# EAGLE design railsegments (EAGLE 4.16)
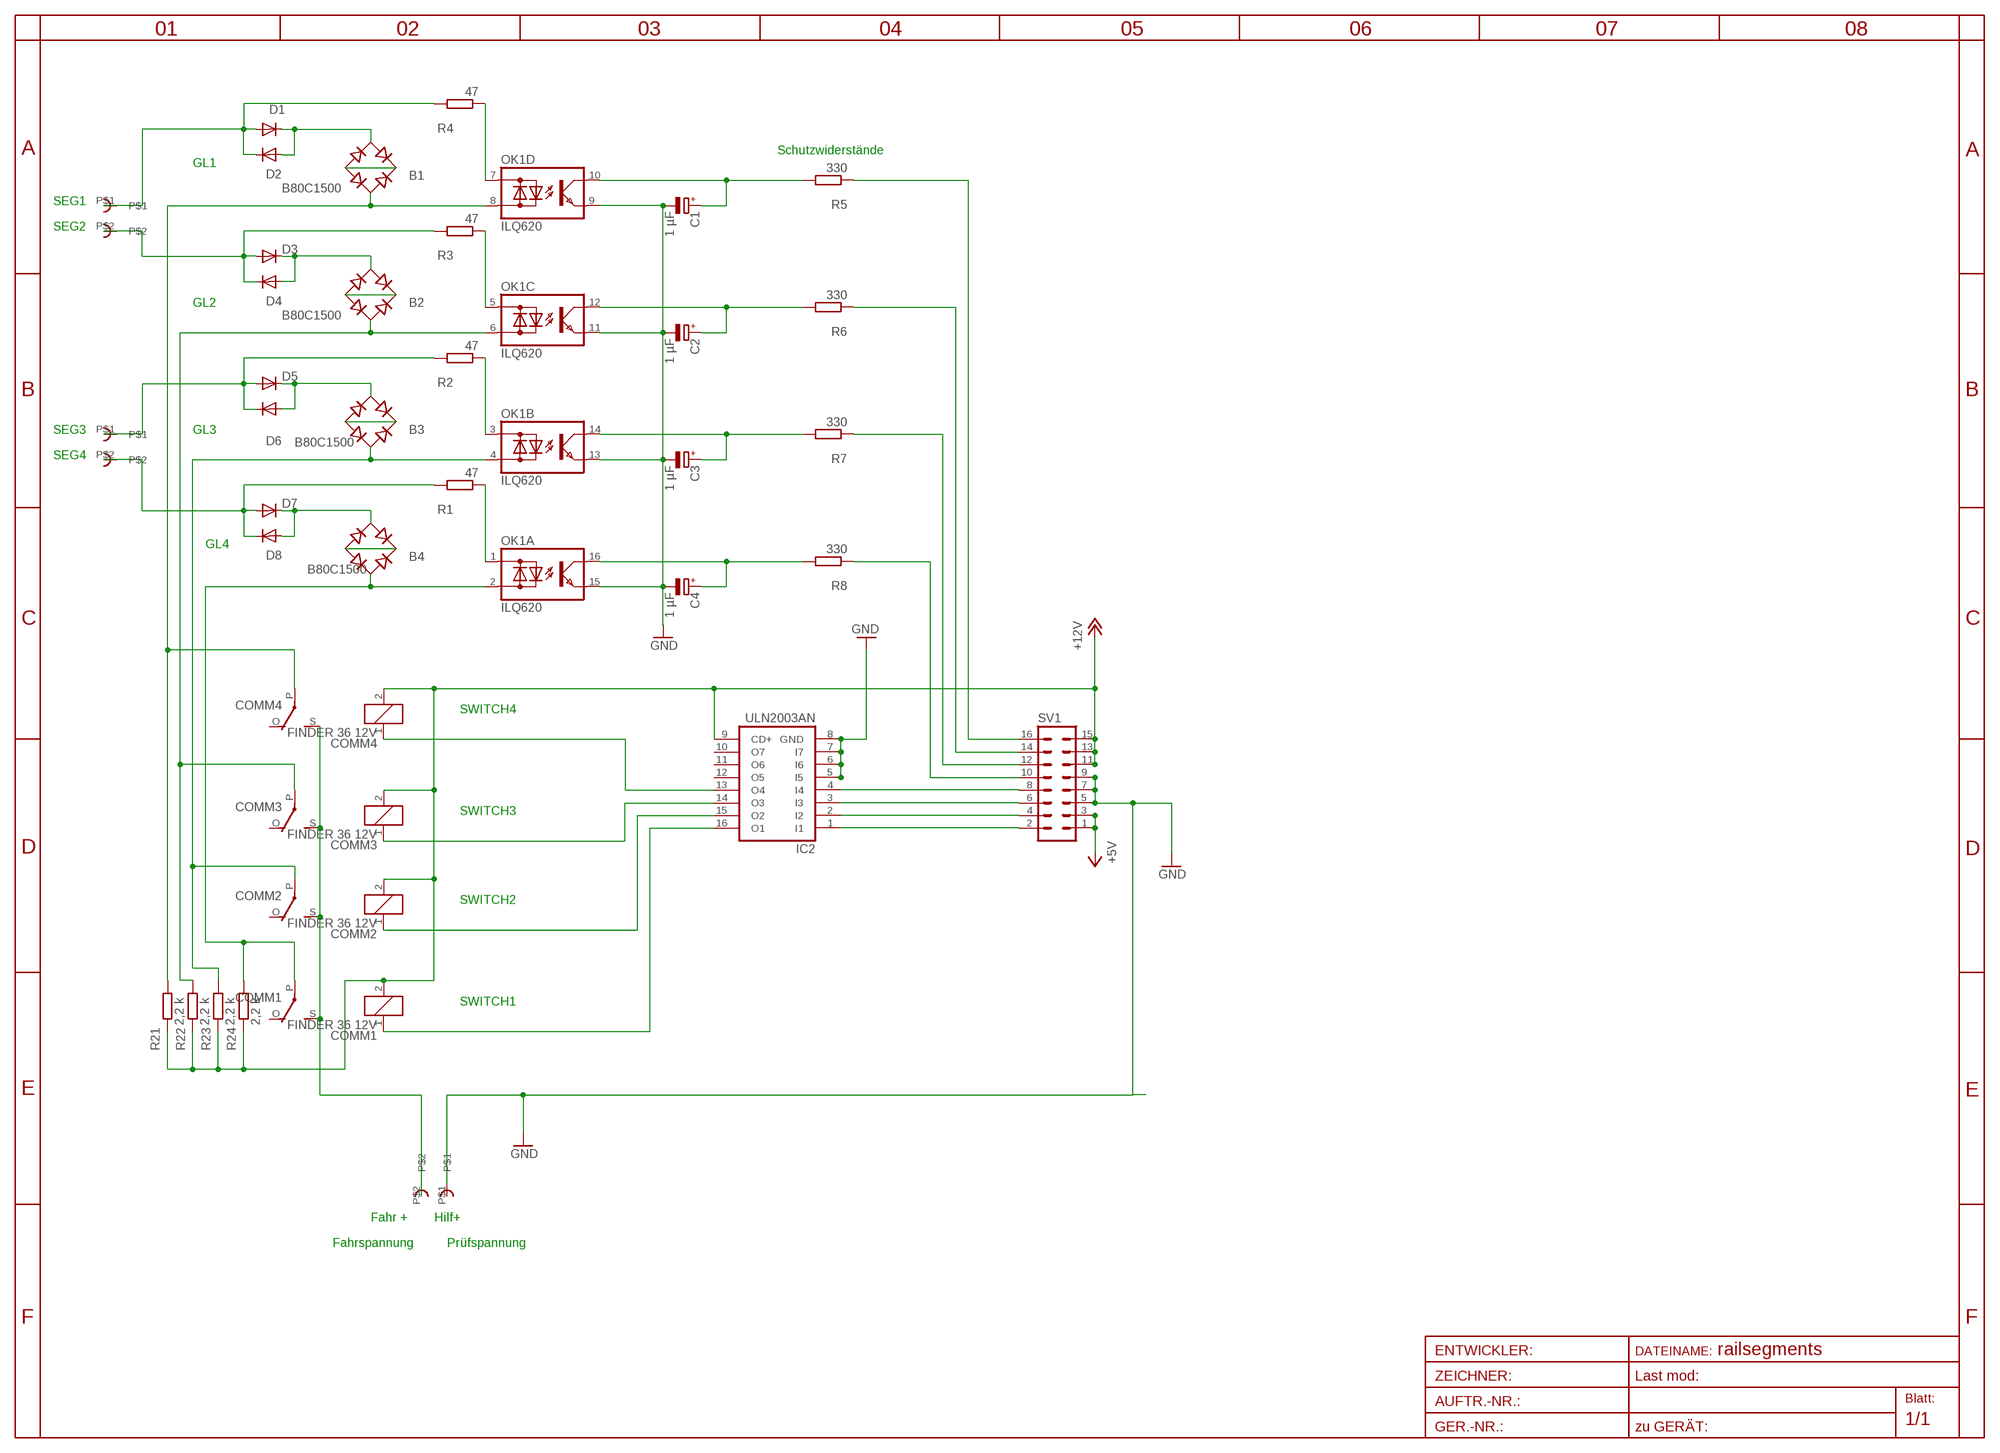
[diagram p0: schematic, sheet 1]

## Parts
B1  B80C1500  RECTIFIER-RB1A  [RB1A]
B2  B80C1500  RECTIFIER-RB1A  [RB1A]
B3  B80C1500  RECTIFIER-RB1A  [RB1A]
B4  B80C1500  RECTIFIER-RB1A  [RB1A]
C1  1 µF  CPOL-EUE2-4  [E2-4]
C2  1 µF  CPOL-EUE2-4  [E2-4]
C3  1 µF  CPOL-EUE2-4  [E2-4]
C4  1 µF  CPOL-EUE2-4  [E2-4]
COMM1  FINDER 36 12V  G5L  [G5LE]
COMM2  FINDER 36 12V  G5L  [G5LE]
COMM3  FINDER 36 12V  G5L  [G5LE]
COMM4  FINDER 36 12V  G5L  [G5LE]
D1  DIODE-D-2.5  [D-2.5]
D2  DIODE-D-2.5  [D-2.5]
D3  DIODE-D-2.5  [D-2.5]
D4  DIODE-D-2.5  [D-2.5]
D5  DIODE-D-2.5  [D-2.5]
D6  DIODE-D-2.5  [D-2.5]
D7  DIODE-D-2.5  [D-2.5]
D8  DIODE-D-2.5  [D-2.5]
IC2  ULN2003AN  [DIL16]
OK1  ILQ620  [DIL16]
PRUEFSPANNUNG  RIACON101-2  [RIACON101-2]
PRUEFSPANNUNG3  RIACON101-2  [RIACON101-2]
PRUEFSPANNUNG4  RIACON101-2  [RIACON101-2]
R1  47  R-EU_0204/5  [0204/5]
R2  47  R-EU_0204/5  [0204/5]
R3  47  R-EU_0204/5  [0204/5]
R4  47  R-EU_0204/5  [0204/5]
R5  330  R-EU_0204/2V  [0204V]
R6  330  R-EU_0204/2V  [0204V]
R7  330  R-EU_0204/2V  [0204V]
R8  330  R-EU_0204/2V  [0204V]
R21  2,2 k  R-EU_0204/2V  [0204V]
R22  2,2 k  R-EU_0204/2V  [0204V]
R23  2,2 k  R-EU_0204/2V  [0204V]
R24  2,2 k  R-EU_0204/2V  [0204V]
SV1  ML16  [ML16]

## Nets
+5V: SV1.1 SV1.3
+12V: COMM1.2 COMM2.2 COMM3.2 COMM4.2 IC2.9(CD+) R21.1 R22.1 R23.1 R24.1 SV1.11 SV1.13 SV1.15
GND: C1.- C2.- C3.- C4.- IC2.5(I5) IC2.6(I6) IC2.7(I7) IC2.8(GND) OK1.9(D:E) OK1.11(C:E) OK1.13(B:E) OK1.15(A:E) SV1.5 SV1.7 SV1.9
IN_1: IC2.1(I1) SV1.2
IN_2: IC2.2(I2) SV1.4
IN_3: IC2.3(I3) SV1.6
IN_4: IC2.4(I4) SV1.8
N$2: OK1.7(D:AC1) R4.1
N$3: OK1.1(A:AC1) R1.1
N$10: B1.+ B1.-
N$11: B2.+ B2.-
N$12: B3.+ B3.-
N$13: B4.+ B4.-
N$17: B1.AC1 D1.C D2.A
N$18: B4.AC1 D7.C D8.A
OPTO_OUT_1: C1.+ OK1.10(D:C) R5.2
OPTO_OUT_2: C2.+ OK1.12(C:C) R6.2
OPTO_OUT_3: C3.+ OK1.14(B:C) R7.2
OPTO_OUT_4: C4.+ OK1.16(A:C) R8.2
OUT_1: R5.1 SV1.16
OUT_2: R6.1 SV1.14
OUT_3: R7.1 SV1.12
OUT_4: R8.1 SV1.10
RAILPOWER_PLUS: COMM1.S(2:S) COMM2.S(2:S) COMM3.S(2:S) COMM4.S(2:S) PRUEFSPANNUNG.P$2
RELAY_DRIVE_1: COMM1.1 IC2.16(O1)
RELAY_DRIVE_2: COMM2.1 IC2.15(O2)
RELAY_DRIVE_3: COMM3.1 IC2.14(O3)
RELAY_DRIVE_4: COMM4.1 IC2.13(O4)
SEG1: D1.A D2.C PRUEFSPANNUNG4.P$1 R4.2
SEG2: B2.AC1 D3.C D4.A
SEG3: B3.AC1 D5.C D6.A
SEG5: D3.A D4.C PRUEFSPANNUNG4.P$2 R3.2
SEG6: D5.A D6.C PRUEFSPANNUNG3.P$1 R2.2
SEG7: D7.A D8.C PRUEFSPANNUNG3.P$2 R1.2
SEG_SW1: B1.AC2 COMM4.P(2:P) OK1.8(D:AC2) R21.2
SEG_SW2: B2.AC2 COMM3.P(2:P) OK1.6(C:AC2) R22.2
SEG_SW2A: OK1.5(C:AC1) R3.1
SEG_SW3: B3.AC2 COMM2.P(2:P) OK1.4(B:AC2) R23.2
SEG_SW3A: OK1.3(B:AC1) R2.1
SEG_SW4: B4.AC2 COMM1.P(2:P) OK1.2(A:AC2) R24.2
Unconnected: COMM1.O(2:O) COMM2.O(2:O) COMM3.O(2:O) COMM4.O(2:O) IC2.10(O7) IC2.11(O6) IC2.12(O5) PRUEFSPANNUNG.P$1

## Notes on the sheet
- Schutzwiderstände
- GL1
- SEG1
- SEG2
- GL2
- SEG3 | GL3
- SEG4
- GL4
- SWITCH4
- SWITCH3
- SWITCH2
- SWITCH1
- Fahr + | Hilf+
- Fahrspannung | Prüfspannung

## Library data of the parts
B1-B4 = rectifier:RECTIFIER-: Rectifier
C1-C4 = rcl:CPOL-EU: POLARIZED CAPACITOR, European symbol
COMM1-COMM4 = relay:G5L: RELAY 1 x switch, 10 A/120 V AC, 8 A/30 V ADC, Omron
D1-D8 = diode:DIODE-: DIODE
IC2 = uln-udn:ULN2003A: DRIVER ARRAY
OK1 = optocoupler:ILQ620: SIEMENS OPTO COUPLER
PRUEFSPANNUNG PRUEFSPANNUNG3 PRUEFSPANNUNG4 = con-riacon101:RIACON101-2: Riaconn Schreaubklemme 101
R1-R8 R21-R24 = rcl:R-EU_: RESISTOR, European symbol
SV1 = con-harting-ml:ML16: HARTING

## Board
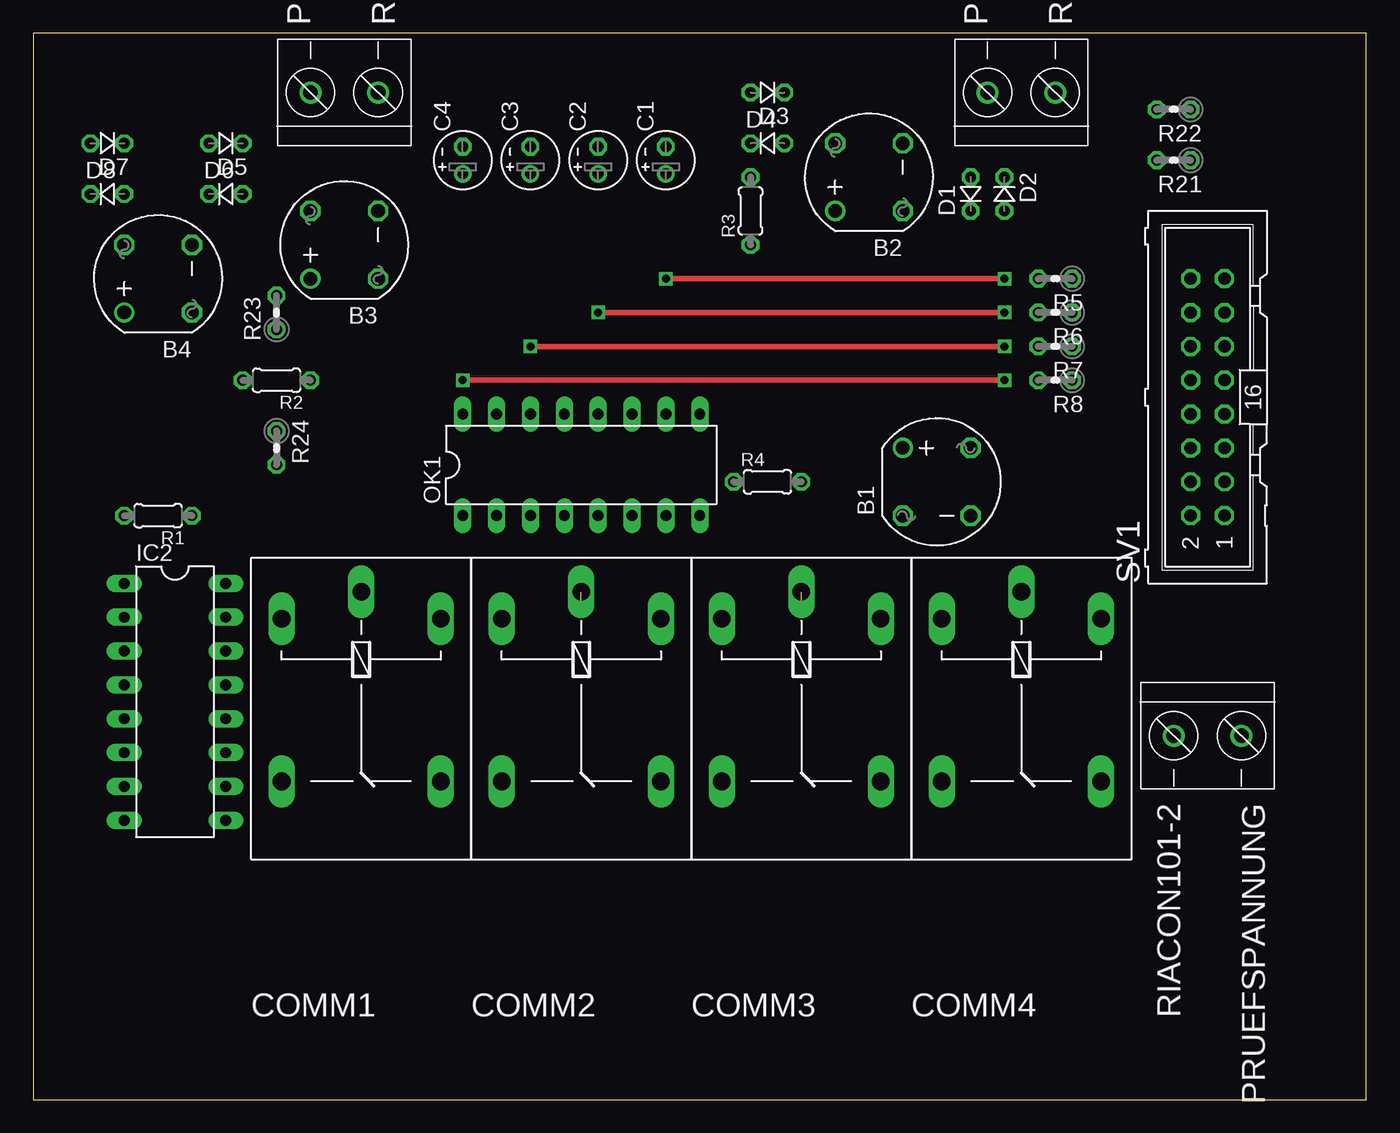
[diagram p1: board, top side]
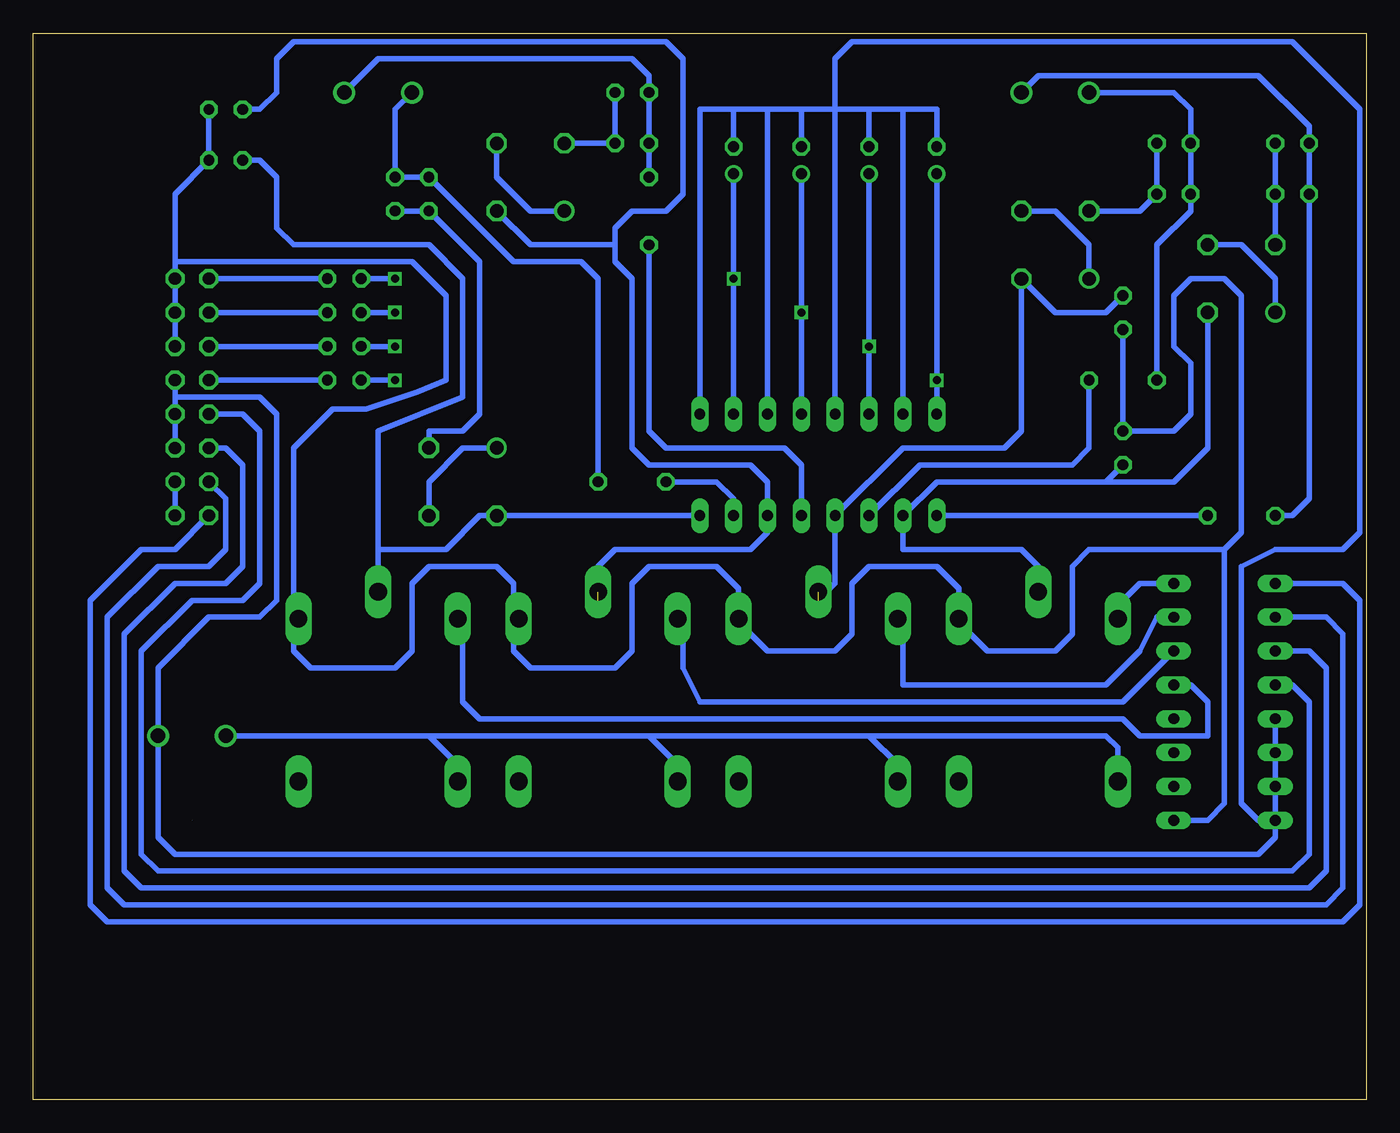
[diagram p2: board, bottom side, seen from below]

Size 100 x 80 mm. Coordinates in mm from the lower left corner, seen from the top.
Outline: 0,0 100,0 100,80 0,80 0,0
Copper layers (1*16): Top 0.035mm / dielectric 1.5mm / Bottom 0.035mm
Design rules "default": minimum track width 10mil, minimum drill 24mil, track to track 8mil, track to pad 8mil, pad to pad 8mil, via to via 8mil, smd to smd 8mil, copper to edge 40mil, drill to drill 8mil, minimum pad ring 10mil, minimum via ring 8mil, stop-mask expansion 4mil, vias tented up to drill 0mil, thermal gap 10mil

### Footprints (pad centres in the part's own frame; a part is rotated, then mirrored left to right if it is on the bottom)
RB1A = drill 1.016 round: + -2.54,2.54 | drill 1.016 octagon: - 2.54,-2.54; AC1 2.54,2.54; AC2 -2.54,-2.54
E2-4 = drill 0.813 pad 1.27 round: + -1.016,0 | drill 0.813 pad 1.27 octagon: - 1.016,0
G5LE = drill 1.321 long: 1 -7.493,-5.969; 2 -7.493,5.969; O 4.699,5.969; P -9.525,0; S 4.699,-5.969
D-2.5 = drill 0.813 octagon: A 1.27,0; C -1.27,0
DIL16 = drill 0.813 long: 1 -8.89,-3.81; 2 -6.35,-3.81; 3 -3.81,-3.81; 4 -1.27,-3.81; 5 1.27,-3.81; 6 3.81,-3.81; 7 6.35,-3.81; 8 8.89,-3.81; 9 8.89,3.81; 10 6.35,3.81; 11 3.81,3.81; 12 1.27,3.81; 13 -1.27,3.81; 14 -3.81,3.81; 15 -6.35,3.81; 16 -8.89,3.81
RIACON101-2 = drill 1.1 round: P$1 0,2.54; P$2 0,-2.54
0204/5 = drill 0.813 octagon: 1 -2.54,0; 2 2.54,0
0204V = drill 0.813 octagon: 1 -1.27,0; 2 1.27,0
ML16 = drill 0.914 octagon: 1 -8.89,-1.27; 2 -8.89,1.27; 3 -6.35,-1.27; 4 -6.35,1.27; 5 -3.81,-1.27; 6 -3.81,1.27; 7 -1.27,-1.27; 8 -1.27,1.27; 9 1.27,-1.27; 10 1.27,1.27; 11 3.81,-1.27; 12 3.81,1.27; 13 6.35,-1.27; 14 6.35,1.27; 15 8.89,-1.27; 16 8.89,1.27

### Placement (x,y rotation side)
B1  67.78,46.35 0 top
B2  62.7,69.21 90 top
B3  23.33,64.13 90 top
B4  9.36,61.59 90 top
C1  47.46,70.48 90 top
C2  42.38,70.48 90 top
C3  37.3,70.48 90 top
C4  32.22,70.48 90 top
COMM1  24.6,28.57 270 top
COMM2  41.11,28.57 270 top
COMM3  57.62,28.57 270 top
COMM4  74.13,28.57 270 top
D1  70.32,67.94 90 top
D2  72.86,67.94 270 top
D3  55.08,75.56 180 top
D4  55.08,71.75 0 top
D5  14.44,71.75 180 top
D6  14.44,67.94 0 top
D7  5.55,71.75 180 top
D8  5.55,67.94 0 top
IC2  10.63,29.84 270 top
OK1  41.11,47.62 0 top
PRUEFSPANNUNG  88.1,27.3 270 top
PRUEFSPANNUNG3  23.33,75.56 90 top
PRUEFSPANNUNG4  74.13,75.56 90 top
R1  9.36,43.81 180 top
R2  18.25,53.97 180 top
R3  53.81,66.67 90 top
R4  55.08,46.35 0 top
R5  76.67,61.59 180 top
R6  76.67,59.05 180 top
R7  76.67,56.51 180 top
R8  76.67,53.97 180 top
R21  85.56,70.48 180 top
R22  85.56,74.29 180 top
R23  18.25,59.05 90 top
R24  18.25,48.89 270 top
SV1  88.1,52.7 90 top

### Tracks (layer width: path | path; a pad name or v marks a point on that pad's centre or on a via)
+5V
  Bottom 0.406: SV1.3 SV1.1
+12V
  Bottom 0.406: SV1.15 SV1.13 | SV1.13 SV1.11 | SV1.15 SV1.13 | R22.1 R21.1 89.37,67.94 89.37,62.86 | R23.1 R24.1 14.44,50.16 13.17,51.43 13.17,55.24 14.44,56.51 14.44,60.32 13.17,61.59 10.63,61.59 9.36,60.32 9.36,42.54 10.63,41.27 | 89.37,62.86 SV1.15 | 80.48,36.19 COMM4.2 80.35,36.06 80.48,36.19 | 80.48,36.19 80.48,48.89 77.56,51.81 75.02,51.81 71.21,53.08 69.05,53.97 69.05,60.32 71.59,62.86 89.37,62.86 | 10.63,41.27 20.79,41.27 22.06,40 22.06,34.92 23.33,33.65 28.41,33.65 30.82,36.06 | 30.82,36.06 30.95,36.19 | 30.82,36.06 COMM1.2 30.57,38.35 32.22,40 37.3,40 38.57,38.73 38.57,34.92 39.84,33.65 44.92,33.65 47.33,36.06 | 47.46,36.19 47.33,36.06 | 47.33,36.06 COMM2.2 47.08,38.35 48.73,40 53.81,40 55.08,38.73 55.08,33.65 56.35,32.38 62.7,32.38 63.97,33.65 63.97,36.19 | COMM3.2 63.84,36.06 63.97,36.19 | IC2.9 11.9,20.95 10.63,22.22 10.63,41.27 | 63.97,36.19 63.97,38.73 65.24,40 70.32,40 71.59,38.73 71.59,33.65 72.86,32.38 79.21,32.38 80.48,33.65 80.48,36.19
GND
  Bottom 0.406: IC2.6 IC2.5 | IC2.7 IC2.6 | 89.37,52.7 SV1.7 SV1.5 89.37,52.7 | 89.37,52.7 83.02,52.7 81.75,51.43 81.75,37.46 83.02,36.19 86.83,36.19 90.64,32.38 90.64,19.68 89.37,18.41 8.09,18.41 6.82,19.68 IC2.8 | 89.37,52.7 SV1.9 | IC2.7 IC2.6 | IC2.8 IC2.7 | IC2.8 8.09,20.95 9.36,22.22 9.36,40 6.82,41.27 1.74,41.27 0.47,42.54 0.47,74.29 5.55,79.37 38.57,79.37 39.84,78.1 39.84,74.29 | C4.- 32.22,74.29 34.76,74.29 | 34.76,74.29 37.3,74.29 | 37.3,74.29 39.84,74.29 | 39.84,74.29 42.38,74.29 | 42.38,74.29 44.92,74.29 | 44.92,74.29 47.46,74.29 | 47.46,74.29 C1.- | 42.38,74.29 C2.- | 37.3,74.29 C3.- | OK1.15 34.76,74.29 | 39.84,74.29 OK1.13 | 44.92,74.29 OK1.11 | OK1.9 50,74.29 47.46,74.29
IN_1
  Bottom 0.406: IC2.1 1.74,38.73 0.47,37.46 0.47,14.6 1.74,13.33 94.45,13.33 95.72,14.6 95.72,37.46 91.91,41.27 89.37,41.27 SV1.2
IN_2
  Bottom 0.406: IC2.2 3.01,36.19 1.74,34.92 1.74,15.87 3.01,14.6 93.18,14.6 94.45,15.87 94.45,36.19 90.64,40 86.83,40 85.56,41.27 85.56,45.08 SV1.4
IN_3
  Bottom 0.406: IC2.3 4.28,33.65 3.01,32.38 3.01,17.14 4.28,15.87 91.91,15.87 93.18,17.14 93.18,34.92 89.37,38.73 85.56,38.73 84.29,40 84.29,47.62 85.56,48.89 SV1.6
IN_4
  Bottom 0.406: IC2.4 5.55,31.11 4.28,29.84 4.28,18.41 5.55,17.14 90.64,17.14 91.91,18.41 91.91,33.65 88.1,37.46 84.29,37.46 83.02,38.73 83.02,50.16 84.29,51.43 SV1.8
N$2
  Bottom 0.406: R4.1 48.73,46.35 47.46,45.08 OK1.7
N$3
  Bottom 0.406: OK1.1 R1.1
N$5  (1 unrouted)
N$10
  Bottom 0.406: B1.+ 67.78,48.89 70.32,46.35 B1.-
N$11
  Bottom 0.406: B2.- 65.24,69.21 62.7,66.67 B2.+
N$12
  Bottom 0.406: B3.+ 20.79,64.13 23.33,66.67 B3.-
N$13
  Bottom 0.406: B4.+ 6.82,61.59 9.36,64.13 B4.-
N$17
  Bottom 0.406: B1.AC1 70.32,50.16 67.78,50.16 66.51,51.43 66.51,62.86 D1.C D2.A
N$18
  Bottom 0.406: D7.C D8.A B4.AC1
OPTO_OUT_1  (via drill 0.6)
  Top 0.406: v47.46,61.59 v72.86,61.59
  Bottom 0.406: OK1.10 v47.46,61.59 C1.+ | v72.86,61.59 R5.2
OPTO_OUT_2  (via drill 0.6)
  Top 0.406: v42.38,59.05 v72.86,59.05
  Bottom 0.406: C2.+ v42.38,59.05 OK1.12 | v72.86,59.05 R6.2
OPTO_OUT_3  (via drill 0.6)
  Top 0.406: v37.3,56.51 v72.86,56.51
  Bottom 0.406: OK1.14 v37.3,56.51 C3.+ | v72.86,56.51 R7.2
OPTO_OUT_4  (via drill 0.6)
  Top 0.406: v32.22,53.97 v72.86,53.97
  Bottom 0.406: OK1.16 v32.22,53.97 C4.+ | v72.86,53.97 R8.2
OUT_1
  Bottom 0.406: R5.1 SV1.16
OUT_2
  Bottom 0.406: R6.1 SV1.14
OUT_3
  Bottom 0.406: R7.1 SV1.12
OUT_4
  Bottom 0.406: R8.1 SV1.10
RAILPOWER_PLUS
  Bottom 0.406: COMM1.S 18.63,26.41 19.52,27.3 37.3,27.3 | 37.3,27.3 53.81,27.3 | 53.81,27.3 70.32,27.3 | 70.32,27.3 PRUEFSPANNUNG.P$2 | COMM2.S 35.14,25.14 37.3,27.3 | COMM3.S 51.65,25.14 53.81,27.3 | COMM4.S 68.16,25.14 70.32,27.3
RELAY_DRIVE_1
  Bottom 0.406: IC2.16 16.98,38.73 18.25,37.46 18.25,36.19 18.38,36.06 COMM1.1
RELAY_DRIVE_2
  Bottom 0.406: IC2.15 15.71,36.19 16.98,33.65 19.52,31.11 34.76,31.11 34.76,36.19 34.89,36.06 COMM2.1
RELAY_DRIVE_3
  Bottom 0.406: IC2.14 18.25,29.84 50,29.84 51.27,32.38 51.27,36.19 51.4,36.06 COMM3.1
RELAY_DRIVE_4
  Bottom 0.406: IC2.13 13.17,31.11 11.9,29.84 11.9,27.3 16.98,27.3 18.25,28.57 66.51,28.57 67.78,29.84 67.78,36.19 67.91,36.06 COMM4.1
SEG1
  Bottom 0.406: PRUEFSPANNUNG4.P$1 72.86,74.29 D2.C D1.A 63.97,62.86 58.89,62.86 57.62,61.59 R4.2
SEG2
  Bottom 0.406: D3.C D4.A B2.AC1
SEG3
  Bottom 0.406: D5.C D6.A 16.98,66.67 B3.AC1
SEG5
  Bottom 0.406: R3.2 D4.C D3.A 53.81,76.83 55.08,78.1 74.13,78.1 PRUEFSPANNUNG4.P$2
SEG6
  Bottom 0.406: PRUEFSPANNUNG3.P$1 14.44,75.56 13.17,74.29 D5.A D6.C 13.17,66.67 15.71,64.13 R2.2
SEG7
  Bottom 0.406: R1.2 5.55,43.81 4.28,45.08 D8.C D7.A 4.28,73.02 8.09,76.83 24.6,76.83 PRUEFSPANNUNG3.P$2
SEG_SW1
  Bottom 0.406: OK1.8 B1.AC2 66.51,43.81 69.05,41.27 74.13,41.27 | R21.2 83.02,70.48 81.75,69.21 81.75,65.4 80.48,64.13 70.32,64.13 67.78,61.59 67.78,52.7 74.13,50.16 74.13,41.27 | 74.13,37.46 COMM4.P 74.13,41.27
SEG_SW2  (1 unrouted)
  Bottom 0.406: B2.AC2 62.7,64.13 56.35,64.13 | 56.35,64.13 56.35,62.86 55.08,61.59 55.08,48.89 53.81,47.62 46.19,47.62 44.92,46.35 OK1.6 44.92,42.54 46.19,41.27 56.35,41.27 57.62,40 57.62,37.46 | R22.2 83.02,74.29 81.75,75.56 81.75,78.1 80.48,79.37 52.54,79.37 51.27,78.1 51.27,67.94 52.54,66.67 55.08,66.67 56.35,65.4 56.35,64.13
SEG_SW2A
  Bottom 0.406: OK1.5 42.38,47.62 43.65,48.89 52.54,48.89 53.81,50.16 R3.1
SEG_SW3  (1 unrouted)
  Bottom 0.406: R23.2 19.52,59.05 23.33,59.05 B3.AC2 25.87,50.16 27.14,48.89 34.76,48.89 OK1.4 39.84,38.73 41.11,37.46
SEG_SW3A
  Bottom 0.406: OK1.3 33.49,47.62 22.06,47.62 20.79,48.89 R2.1
SEG_SW4
  Bottom 0.406: COMM1.P 24.6,40 25.87,41.27 34.76,41.27 OK1.2 32.22,46.35 19.52,46.35 | B4.AC2 11.9,48.89 14.44,46.35 19.52,46.35 | 19.52,46.35 R24.2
